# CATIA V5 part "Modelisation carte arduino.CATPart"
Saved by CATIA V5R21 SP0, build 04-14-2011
Part number: Modélisation Carte Arduino
Bounding box of the stored display mesh (mm): x 0 to 106.6, y 0 to 53.3, z 0 to 13
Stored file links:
  C:\Users\2027.DESARCY-LEMIE30\Desktop\V16(05.04.2023)\Modelisation carte arduino.CATPart
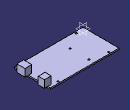
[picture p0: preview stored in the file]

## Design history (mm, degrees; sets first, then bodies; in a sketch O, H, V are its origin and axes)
Body1 (main body)
  Sketch1 on xy-plane, origin (0, 0, 0), H (1, 0, 0), V (0, 1, 0)
    line L1 (0, 53.3) -> (101.6, 53.3)
    line L2 (101.6, 53.3) -> (101.6, 0)
    line L3 (101.6, 0) -> (0, 0)
    line L4 (0, 0) -> (0, 53.3)
    point P4 (0, 0)
    length L3 = 101.6
    length L2 = 53.3
    horizontal: L1 H, L3 H
    vertical: L2 V, L4 V
    coincidence: P4 O
  Pad1: profile Sketch1, direction (0, 0, 1), length 2
  Sketch2 on face of Pad1 from Sketch1.L2, origin (101.6, 0, 0), H (0, 1, 0), V (0, 0, 1)
    line L1 (8.8, 13) -> (20.8, 13)
    line L2 (20.8, 13) -> (20.8, 2)
    line L3 (20.8, 2) -> (8.8, 2)
    line L4 (8.8, 2) -> (8.8, 13)
    reference projected line E1 (0, 2) -> (53.3, 2) from edge [face of Pad1 from Sketch1.L2 | end face of Pad1]
    line L5 (40.5, 13) -> (49.5, 13)
    line L6 (49.5, 13) -> (49.5, 2)
    line L7 (49.5, 2) -> (40.5, 2)
    line L8 (40.5, 2) -> (40.5, 13)
    reference projected line E2 (0, 2) -> (53.3, 2) from edge [face of Pad1 from Sketch1.L2 | end face of Pad1]
    distance L4 V = 8.8
    length L1 = 12
    length L2 = 11
    distance L2 L8 = 19.7
    length L5 = 9
    length L8 = 11
    horizontal: L1 H, L3 H, L5 H, L7 H
    vertical: L2 V, L4 V, L6 V, L8 V
    coincidence: L3 E1, E2 L7
  Pad2: profile Sketch2, direction (1, 0, 0), length 5, opposite side length 5
  Sketch3 on xy-plane, origin (0, 0, 0), H (1, 0, 0), V (0, 1, 0)
    circle A1 centre (87.6, 2.5) radius 1.3
    point P1 (87.6, 2.5)
    circle A2 centre (12.7, 2.5) radius 1.3
    point P2 (12.7, 2.5)
    circle A3 centre (87.6, 50.7) radius 1.3
    point P3 (87.6, 50.7)
    circle A4 centre (12.7, 50.7) radius 1.3
    point P4 (12.7, 50.7)
    reference projected line E1 (101.6, 0) -> (101.6, 53.3) from edge [face of Pad1 from Sketch1.L2 | end face of Pad1]
    circle A5 centre (36.8, 17.7) radius 1.3
    point P5 (36.8, 17.7)
    circle A6 centre (36.8, 45.6) radius 1.3
    point P6 (36.8, 45.6)
    reference projected line E2 (0, 0) -> (101.6, 0) from edge [face of Pad1 from Sketch1.L3 | end face of Pad1]
    construction line L1 (104.2729, 2.5) -> (-3.8985, 2.5)
    construction line L2 (36.8, 7.0859) -> (36.8, 48.7575)
    construction line L3 (110.6573, 50.7) -> (14.6616, 50.7)
    construction line L4 (87.6, -3.0536) -> (87.6, 62.1687)
    axis line L5 (12.7, -7.199) -> (12.7, 65.513)
    radius A4 = 1.3
    radius A3 = 1.3
    radius A1 = 1.3
    radius A2 = 1.3
    distance P1 E1 = 14
    radius A5 = 1.3
    radius A6 = 1.3
    distance P5 P2 V = 15.2
    distance P2 E2 = 2.5
    distance P5 P2 H = 24.1
    distance P2 P1 H = 74.9
    distance P5 P6 = 27.9
    distance P6 P4 V = 5.1
    horizontal: L1 H, L3 H
    coincidence: P2 L1, P1 L1, L2 P5, P6 L2, P4 L3, P3 L3, P3 L4, L4 P1, P4 L5, L5 P2
    vertical: L2 V, L4 V, L5 V
  Pocket1: profile Sketch3, direction (0, 0, -1), through (limit type 3)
